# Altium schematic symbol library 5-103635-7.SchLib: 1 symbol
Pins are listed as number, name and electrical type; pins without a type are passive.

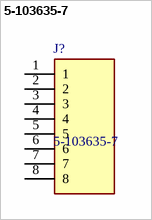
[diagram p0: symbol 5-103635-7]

## 5-103635-7
designator J?
Body Features: Primary Product Color Black | Configuration Features: Number of Rows 1 | Number of Positions 8 | PCB Mount Orientation Right Angle | Contact Features: PCB Contact Termination Area Plating Material Thickness 2.54 MICM | Contact Type Pin | Mating Square Post Dimension .64 MM | Contact Mating Area Plating Material Thickness .381 MICM | Contact Shape & Form Square | Mating Square Post Dimension .025 INCH | PCB Contact Termination Area Plating Material Finish Matte | Contact Mating Area Plating Ma; Manufacturer_Name: TE Connectivity; Geometry.Height: 7.41mm
footprint SHDRRA8W50P0X254_1X8_2273X1359X741P
pins: 1, 2, 3, 4, 5, 6, 7, 8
